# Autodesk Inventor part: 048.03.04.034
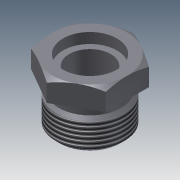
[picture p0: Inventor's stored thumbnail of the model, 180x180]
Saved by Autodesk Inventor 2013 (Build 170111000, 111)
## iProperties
Shininess: 20.0
Angle Display Precision: 2
Document Length Units: 11269
Document Angle Units: 11279
Document Time Units: 11290
Document Mass Units: 11283
Document Length Units Precision: 3
Document Angle Units Precision: 2
Created: 2002-08
Part Number: 048.03.04.034
Material: Steel, Mild
Document SubType Name: Modeling
Designer: SOleg
Mass: 121.294 g
Surface Area: 67.9132 cm^2
Volume: 15.4318 cm^3
Density: 7.86 g/cm^3
Density: 0.0
Volumn: 0.0
Area: 0.0
PropertySet Name: Model Information
Control State: 0
Master: False
Checked Out: True
Checked Out Date: 2008-10-15
Last Check In Date: 2008-10-15
Author: SOleg
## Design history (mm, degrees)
node "WorkPlane1"
node "WorkPlane2"
node "WorkPlane7"
revolve "Вращение3" stored, may be unused: angle "d84" = 90 deg
feature "Резьба2" dims "d85" = 10, "d86" = 0
sketch "Эскиз9"
  geometry: L1 (0, -20.785)-(-18, -10.392); L2 (-18, -10.392)-(-18, 10.392); L3 (-18, 10.392)-(0, 20.785); L4 (0, 20.785)-(18, 10.392); L5 (18, 10.392)-(18, -10.392); L6 (18, -10.392)-(0, -20.785); C1 r 18 at (0, 0) reference; 1 further point
  constraints: 12 end point, 1 coincident, 11 other
  dimensions: "d87" = 36 distance between parallel lines of L3 L6
extrude "Выдавливание4" sketch "Эскиз9" stored distance "d88" = 10; taper "d89" = 0 deg
body "Solid1"
sketch "Эскиз8"
  geometry: L1 (0.578, -6.289)-(-17.422, -6.289); L2 (-17.422, -6.289)-(-24.422, -10.33); L3 (-24.422, -10.33)-(-24.422, -16.289); L4 (-24.422, -16.289)-(-14.422, -16.289); L5 (-14.422, -16.289)-(-14.422, -21.289); L6 (-14.422, -21.289)-(-15.922, -22.789); L7 (-15.922, -22.789)-(-15.922, -34.289); L8 (-15.922, -34.289)-(-13.922, -36.289); L9 (-13.922, -36.289)-(0.578, -36.289); L10 (0.578, -36.289)-(0.578, -6.289); L11 (-12.922, -36.289)-(-9.422, -25.828); L12 (-9.422, -25.828)-(-9.422, -11.289); L13 (-9.422, -11.289)-(-12.422, -11.289); L14 (-12.422, -11.289)-(-12.422, -6.289)
  constraints: 28 end point, 6 parallel, 4 perpendicular, 2 point on line, 1 horizontal, 1 other
  dimensions: "d69" = 5 distance of L4.end L5.end; "d70" = 45 deg angle of L7 L6; "d71" = 2 horizontal distance of L7.end L8.end; "d72" = 30 diameter of L5 L10; "d73" = 33 diameter of L7 L10; "d74" = 27 diameter of L11.start L10; "d75" = 20 diameter of L12 L10; "d76" = 18.5 deg angle of L11 L12; "d77" = 26 diameter of L14 L10; "d78" = 5 distance of L13.end L14.end; "d79" = 20 distance between parallel lines of L4 L9; "d80" = 30 distance between parallel lines of L1 L9; "d81" = 30 deg angle of L2 L1; "d82" = 36 diameter of L1.end L10; "d83" = 50 diameter of L3 L10
other parameters: "d0" = 0, "d3" = 0 (derived), "d6" = 135 deg (derived), "d8" = 15.7 (derived), "d10" = 16.5 (derived), "d12" = 5 (derived), "d14" = 0.5 (derived), "d16" = 135 deg (derived), "d18" = 15 (derived), "d24" = 60 deg (derived), "d26" = 36 (derived), "d28" = 36 (derived), "d30" = 20.78461 (derived), "d32" = 20.78461 (derived), "d34" = 120 deg (derived), "d36" = 120 deg (derived), "d42" = 1 (derived), "d44" = 0 (derived), "d45" = 45 deg (derived), "d48" = 26 (derived), "d52" = 19 (derived)
